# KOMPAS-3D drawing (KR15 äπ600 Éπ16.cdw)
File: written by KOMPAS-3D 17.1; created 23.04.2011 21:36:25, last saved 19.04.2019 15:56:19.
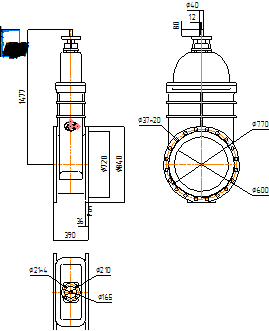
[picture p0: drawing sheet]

Sheet 1: A4, portrait

Title block, sheet 1: name: KR15 Ду600 Ру16; material: Внимание! Данный продукт является объектом авторского права ООО «Торговый Дом АДЛ». / Запрещается изменение, копирование, распространение / (в том числе путем копирования на другие сайты и ресурсы в Интернете) / или любое иное использование информации и объектов без предварительного / согласия правообладателя (ООО «Торговый Дом АДЛ»).; scale: 1:1; sheets: 1; organisation: ООО "Торговый дом АДЛ"; sheet format: A4; stored path: \\adlc.lan\data\АДЛ_ПКД\3D-модели\ADL production\Клиновые задвижки серии KR ГРАНАР\Клиновые задвижки KR15\С голым штоком\KOMPAS 2D\KR15 Ду600 Ру16.cdw

Views: Спереди 4, Проекционный вид 5
Dimensions and other numbers on the sheet: 840; 720; 1477; 390; 36; 5; 21; 210; 165; 1:1; 1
